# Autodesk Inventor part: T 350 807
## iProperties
Company: Mayer & Müller AG Schaltgeräte
Created: 2005-12
Part Number: T 350 807
Material: 2.0060.30
Document SubType Name: Blech
Designer: I.Baliuc
Manufacturer: Standard
Standards Organization: Custom
Description: Stromschiene
Density: 8.94 g/cm^3
Sheet Metal Rule: Standard
HalbzeugNorm: DIN 1759
Zweck: für Spannungsanschluß LBK
Abmessung: 20 x 8 - 155,5
Author: T.Messerschmitt
Keywords: 267155
Revision Number: 350807
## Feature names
1. Bohrung_M6_a [Hole]
2. Bohrung_Ø6.2 [Hole]
3. Bohrung_M6_b [Hole]
4. Rundung1 [Fillet]
5. Grobblech3
6. Biegung2
7. ExtrusionAbwicklung2
